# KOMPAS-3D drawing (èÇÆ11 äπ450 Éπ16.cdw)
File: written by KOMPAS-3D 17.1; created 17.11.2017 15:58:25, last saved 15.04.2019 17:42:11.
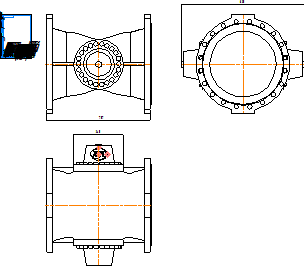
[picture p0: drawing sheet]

Sheet 1: A4, portrait

Title block, sheet 1: name: КАТ11 Ду450 Ру16; material: Внимание! Данный продукт является объектом авторского права ООО «Торговый Дом АДЛ». / Запрещается изменение, копирование, распространение / (в том числе путем копирования на другие сайты и ресурсы в Интернете) / или любое иное использование информации и объектов без предварительного / согласия правообладателя (ООО «Торговый Дом АДЛ»).; mass: 12,4; sheets: 1; organisation: ООО "Торговый дом АДЛ"; sheet format: A4; stored path: \\adlc.lan\data\АДЛ_ПКД\3D-модели\ADL production\Клапаны КАТ ГРАНРЕГ\КАТ11\KOMPAS 2D\КАТ11 Ду450 Ру16.cdw

Views: Вид 1, Проекционный вид 2, Проекционный вид 3
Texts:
  kka
  adl
Dimensions and other numbers on the sheet: 707; 830; 340; 1:1; 1; 12,4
